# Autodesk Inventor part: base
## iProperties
Created: 2009-04
Part Number: base
Document SubType Name: Modeling
Designer: Lochan
Density: 1 g/cm^3
Author: Lochan
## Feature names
1. Extrusion1
2. Extrusion2
3. Extrusion3
